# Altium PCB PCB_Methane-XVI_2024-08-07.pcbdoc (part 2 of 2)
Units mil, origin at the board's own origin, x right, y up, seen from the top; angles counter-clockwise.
Board outline 4553.3 x 5155.85 mil, 2 copper layers (Top Layer, Bottom Layer); 67 components, 58 nets, 315 pads, 114 vias.
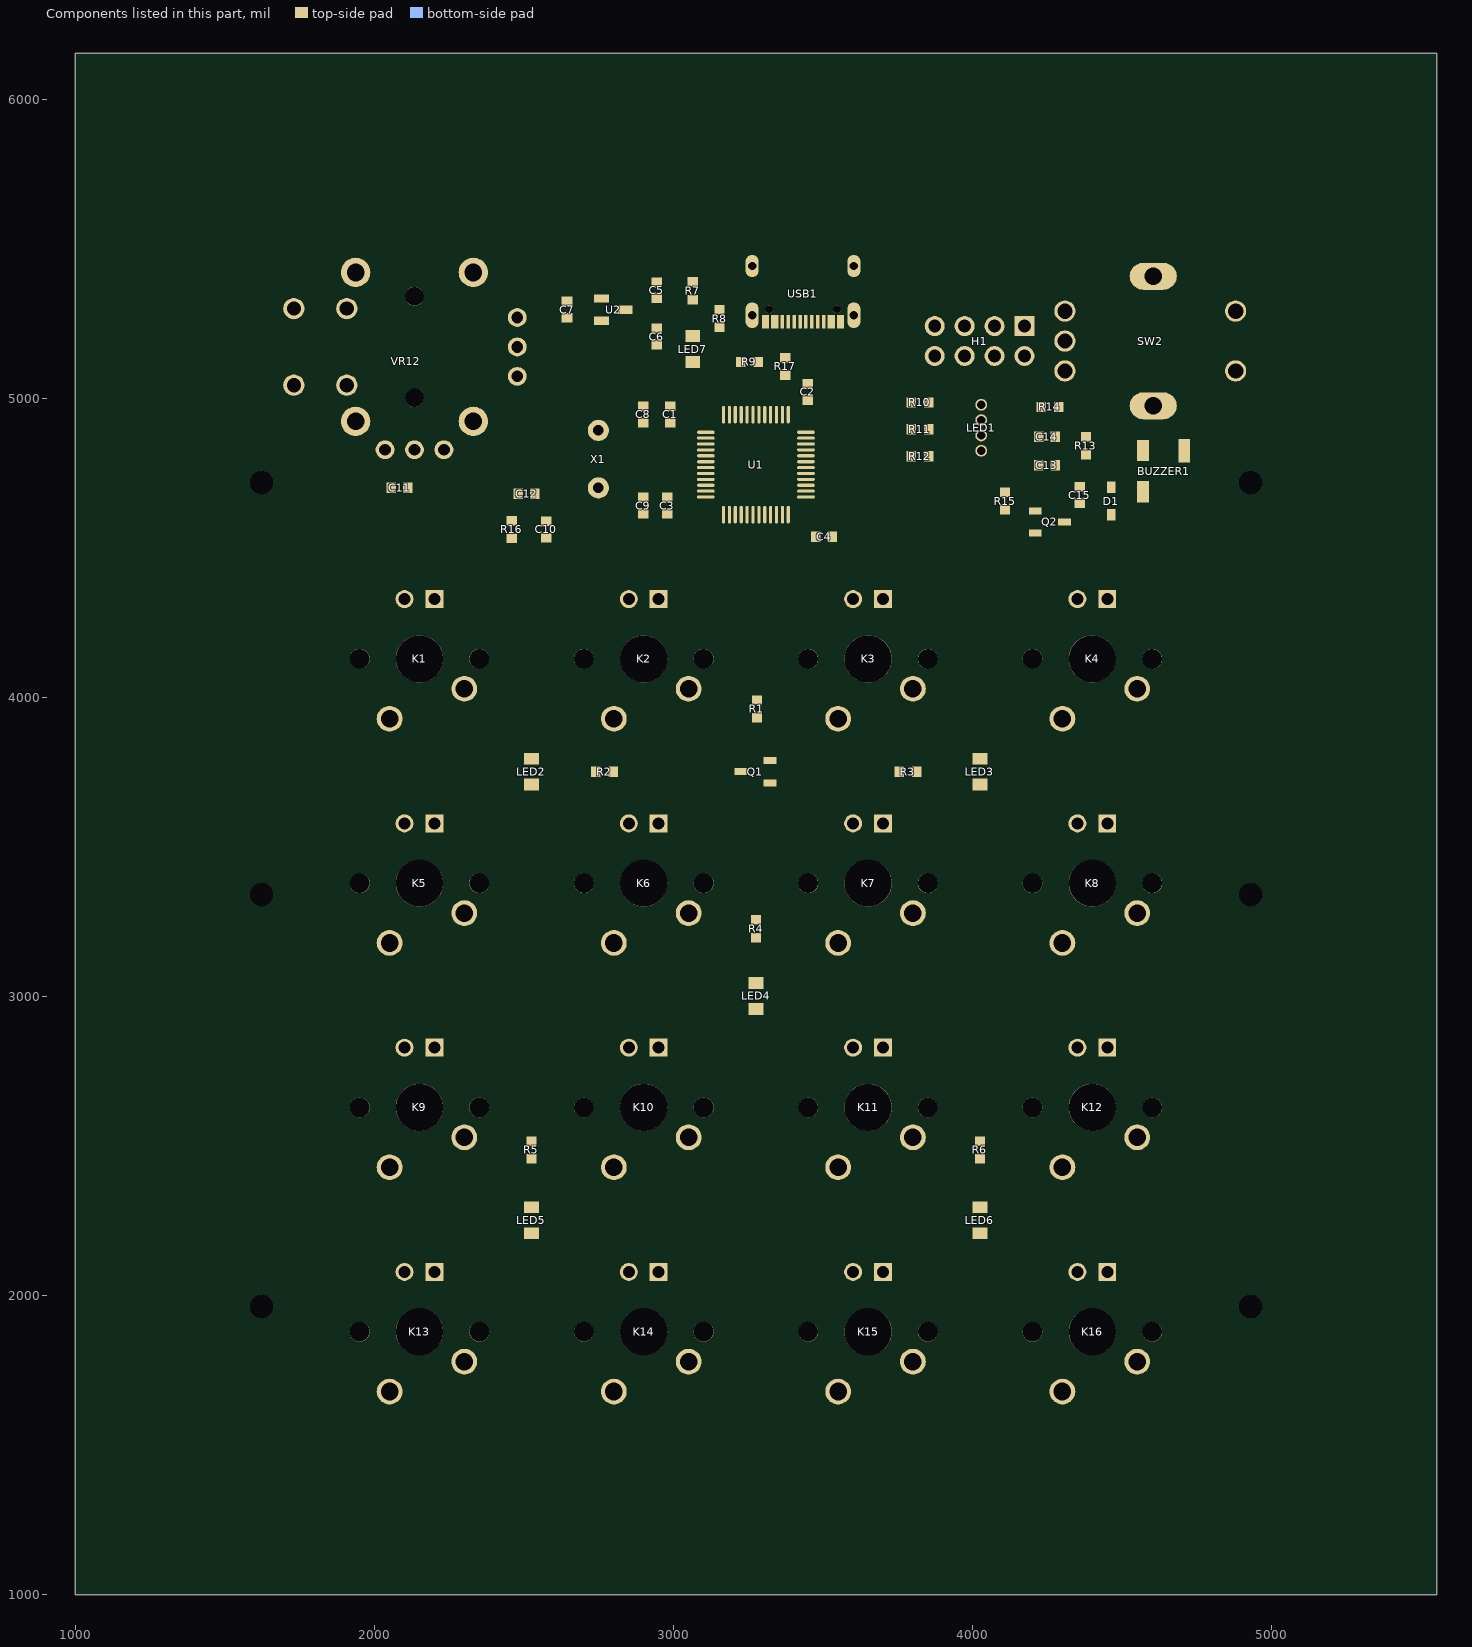
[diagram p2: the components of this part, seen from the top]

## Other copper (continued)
Bottom Layer:
  pour cut-out net S$53996: 4985,4892.94 4913.79,4821.73 4865.9,4821.73 4830,4785.83 4830,4647.94 4865,4612.94 4915,4612.94 4985,4542.94 5010,4542.94 5010,4567.94 5010,4892.94
  pour cut-out net S$53996: 4985,3514.99 4913.79,3443.78 4865.9,3443.78 4830,3407.88 4830,3269.99 4865,3234.99 4915,3234.99 4985,3164.99 5010,3164.99 5010,3189.99 5010,3514.99
  pour cut-out net S$53996: 4985,2137.04 4913.79,2065.83 4865.9,2065.83 4830,2029.93 4830,1892.04 4865,1857.04 4915,1857.04 4985,1787.04 5010,1787.04 5010,1812.04 5010,2137.04
  pour cut-out net S$53996: 1568.3,4548.14 1639.51,4619.35 1687.39,4619.35 1723.3,4655.25 1723.3,4793.14 1688.3,4828.14 1638.3,4828.14 1568.3,4898.14 1543.3,4898.14 1543.3,4873.14 1543.3,4548.14
  pour cut-out net S$53996: 1568.3,3170.19 1639.51,3241.4 1687.39,3241.4 1723.3,3277.3 1723.3,3415.19 1688.3,3450.19 1638.3,3450.19 1568.3,3520.19 1543.3,3520.19 1543.3,3495.19 1543.3,3170.19
  pour cut-out net S$53996: 1568.3,1792.24 1639.51,1863.45 1687.39,1863.45 1723.3,1899.35 1723.3,2037.24 1688.3,2072.24 1638.3,2072.24 1568.3,2142.24 1543.3,2142.24 1543.3,2117.24 1543.3,1792.24
  region net +5V: 3899.78,5120.84 3849.58,5120.84 3864.68,5097.42 3884.68,5097.42
  region net +5V: 3865.78,5175.24 3843.78,5130.12 3828.85,5152.94 3838.6,5172.94
  region net KEY1: 2330.11,3997.77 2330.07,4062.27 2360.19,4035.04 2360.2,4025.04
  region net KEY2: 3080.11,3997.77 3080.07,4062.27 3110.19,4035.04 3110.2,4025.04
  region net KEY3: 3830.11,3997.77 3830.07,4062.27 3860.19,4035.04 3860.2,4025.04
  region net KEY4: 4554.34,3987.08 4508.73,4032.69 4506.72,3992.14 4513.79,3985.07
  region net KEY5: 2330.11,3247.77 2330.07,3312.27 2360.19,3285.04 2360.2,3275.04
  region net KEY6: 3080.11,3247.77 3080.07,3312.27 3110.19,3285.04 3110.2,3275.04
  region net KEY7: 3804.34,3237.08 3758.73,3282.69 3756.72,3242.14 3763.79,3235.07
  region net KEY8: 4554.34,3237.08 4508.73,3282.69 4506.72,3242.14 4513.79,3235.07
  region net KEY9: 2330.11,2497.77 2330.07,2562.27 2360.19,2535.04 2360.2,2525.04
  region net KEY10: 3080.09,2497.75 3080.09,2562.25 3110.19,2535 3110.19,2525
  region net KEY11: 3804.34,2487.08 3758.73,2532.69 3756.72,2492.14 3763.79,2485.07
  region net KEY12: 4554.34,2487.08 4508.73,2532.69 4506.72,2492.14 4513.79,2485.07
  region net KEY13: 2330.11,1747.77 2330.07,1812.27 2360.19,1785.04 2360.2,1775.04
  region net KEY14: 3080.11,1747.77 3080.07,1812.27 3110.19,1785.04 3110.2,1775.04
  region net KEY15: 3830.11,1747.77 3830.07,1812.27 3860.19,1785.04 3860.2,1775.04
  region net KEY16: 4580.11,1747.77 4580.07,1812.27 4610.19,1785.04 4610.2,1775.04
  region net ANA1: 2132.96,4798.16 2166.35,4831.58 2168.79,4802.82 2161.72,4795.75
  region net 3V3: 2231.37,4798.16 2264.77,4831.56 2270.73,4806.34 2256.59,4792.2
  region net ANA2: 2447.18,5175.25 2480.61,5141.86 2451.85,5139.42 2444.78,5146.49
  region net 3V3: 2476.65,5106.29 2510.05,5072.89 2516.01,5098.11 2501.87,5112.25
  region net U1_7: 2971,4740 2989,4740 2985,4731.6 2975,4731.6
  region net KEY6: 3221,4400 3239,4400 3235,4391.6 3225,4391.6
  region net KEY10: 3251,4365 3269,4365 3265,4356.6 3255,4356.6
  region net KEY15: 3281,4400 3299,4400 3295,4391.6 3285,4391.6
  region net KEY11: 3311,4365 3329,4365 3325,4356.6 3315,4356.6
  region net KEY7: 3341,4400 3359,4400 3355,4391.6 3345,4391.6
  region net KEY2: 3191,4365 3209,4365 3205,4356.6 3195,4356.6
  region net KEY14: 3142.06,4413.94 3142.06,4431.94 3133.66,4427.94 3133.66,4417.94
  region net KEY13: 3110.2,4441.94 3104.69,4459.08 3097.84,4452.94 3101.05,4442.94
  region net ANA1: 3071,4615 3089,4615 3085,4606.6 3075,4606.6
  region net ANA2: 3040.75,4590.96 3028.02,4603.69 3024.91,4594.92 3031.98,4587.85
  region net SWDIO: 3474.14,4938.41 3491.12,4932.45 3490.65,4941.52 3480.18,4945.19
  region net SWCLK: 3412.94,4943.94 3412.94,4961.94 3421.34,4957.94 3421.34,4947.94
  region net SWDIO: 3562.06,4938.94 3562.06,4956.94 3553.66,4952.94 3553.66,4942.94
  region net SWCLK: 3570.75,4985.96 3558.02,4998.69 3554.91,4989.92 3561.98,4982.85
  region net EC2: 3397.94,4993.94 3397.94,5011.94 3406.34,5007.94 3406.34,4997.94
  region net EC1: 3367.94,5018.94 3367.94,5036.94 3376.34,5032.94 3376.34,5022.94
  region net EC2: 3610.75,5065.96 3598.02,5078.69 3594.91,5069.92 3601.98,5062.85
  region net EC1: 3565.75,5060.96 3553.02,5073.69 3549.91,5064.92 3556.98,5057.85
  region net KEY18: 3337.94,5043.94 3337.94,5061.94 3346.34,5057.94 3346.34,5047.94
  region net KEY18: 3560.75,5100.96 3548.02,5113.69 3544.91,5104.92 3551.98,5097.85
  region net U1_7: 2852.94,4593.94 2852.94,4611.94 2861.34,4607.94 2861.34,4597.94
  region net KEY1: 3166,4795 3184,4795 3180,4786.6 3170,4786.6
  region net KEY5: 3201,4755 3219,4755 3215,4746.6 3205,4746.6
  region net KEY9: 3236,4810 3254,4810 3250,4801.6 3240,4801.6
  region net KEY16: 3667.94,4618.94 3667.94,4636.94 3676.34,4632.94 3676.34,4622.94
  region net KEY12: 3702.94,4648.94 3702.94,4666.94 3711.34,4662.94 3711.34,4652.94
  region net KEY8: 3737.94,4678.94 3737.94,4696.94 3746.34,4692.94 3746.34,4682.94
  region net KEY4: 3772.94,4708.94 3772.94,4726.94 3781.34,4722.94 3781.34,4712.94
  region net LEDG: 3341.98,4878.69 3329.25,4865.96 3338.02,4862.85 3345.09,4869.92
  region net LEDR: 3386.98,4883.69 3374.25,4870.96 3381.46,4869.4 3388.54,4876.48
  region net 3V3: 3451.98,4918.69 3439.25,4905.96 3444.48,4899.32 3458.62,4913.46
  region net 3V3: 3432.06,4908.94 3432.06,4926.94 3423.66,4927.94 3423.66,4907.94
  region net KEY3: 3291,4735 3309,4735 3305,4726.6 3295,4726.6
  region net GATE: 3371,4365 3389,4365 3385,4356.6 3375,4356.6
  region net GATE: 3371,4095.88 3389,4095.88 3385,4104.28 3375,4104.28
  region net LEDB: 3367.94,4523.94 3367.94,4541.94 3376.34,4537.94 3376.34,4527.94
  region net LEDB: 3680.75,4770.96 3668.02,4783.69 3664.91,4774.92 3671.98,4767.85
  region net LEDR: 3630.75,4815.96 3618.02,4828.69 3614.91,4819.92 3621.98,4812.85
  region net LEDG: 3635.75,4770.96 3623.02,4783.69 3619.91,4774.92 3626.98,4767.85
  region net 3V3: 3790.75,5090.96 3778.02,5103.69 3771.38,5098.46 3785.52,5084.32
  region net 3V3: 3120.01,4955.88 3102.01,4955.87 3101.01,4964.27 3121.01,4964.28
  region net 3V3: 3551.98,4582.19 3539.25,4594.92 3544.48,4601.56 3558.62,4587.42
  region net +5V: 3530.75,5150.96 3518.02,5163.69 3511.38,5158.46 3525.52,5144.32
  region net +5V: 3537.94,5153.94 3537.94,5171.94 3546.34,5172.94 3546.34,5152.94
  region net +5V: 3936,4675.88 3954,4675.88 3955,4684.28 3935,4684.28
  region net +5V: 3145.75,5109.92 3133.02,5097.19 3126.38,5102.42 3140.52,5116.56
  region net +5V: 3152.94,5088.94 3152.94,5106.94 3161.34,5107.94 3161.34,5087.94
  region net 3V3: 2356,4660.88 2374,4660.88 2375,4669.28 2355,4669.28
  region net 3V3: 3260.75,5050.96 3248.02,5063.69 3241.38,5058.46 3255.52,5044.32
  region net 3V3: 3251,5055 3269,5055 3270,5047.94 3250,5047.94
  region net +5V: 3132.18,5123.7 3119.24,5110.76 3124.68,5104.12 3138.82,5118.26
  region net +5V: 3120.76,5135.12 3107.82,5122.18 3101.18,5127.62 3115.32,5141.76
  region net +5V: 2993.07,5278.79 2993.07,5297.09 3001.62,5297.94 3001.62,5277.94
  region net +5V: 3006.93,5278.79 3006.93,5297.09 2998.38,5297.94 2998.38,5277.94
  region net +5V: 3027.18,5288.7 3014.24,5275.76 3019.68,5269.12 3033.82,5283.26
  region net ANA2: 2441.93,4673.79 2441.93,4692.09 2433.38,4687.94 2433.38,4677.94
  region net 3V3: 2680.85,5219.87 2699.15,5219.87 2700,5211.32 2680,5211.32
  region net 3V3: 2680.85,5191.31 2699.15,5191.31 2700,5199.86 2680,5199.86
  region net 3V3: 2691.03,5171.08 2677.81,5183.74 2668.07,5181.24 2688.95,5161.24
  region net 3V3: 2702.19,5183.74 2688.97,5171.08 2691.05,5161.24 2711.93,5181.24
  region net +5V: 4016.98,4913.77 4016.98,4943.29 4003.2,4938.53 4003.2,4918.53

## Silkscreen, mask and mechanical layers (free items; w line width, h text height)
Top Overlay:
  text "DIO" at 3950,5317.94 h30
  text "CLK" at 4035,5317.94 h30
  text "3V3" at 3735,5207.94 h30
  text "GND" at 4270,5157.94 h30 r90
  text "5V" at 3745,5107.94 h30
  text "RX" at 3950,5032.94 h30
  text "TX" at 4050,5032.94 h30
  text "Methane-XVI" at 1810,4507.94 h50
Bottom Overlay:
  text "Designed by / light&electricity / V4.0" at 4745,4707.94 h50
Top Solder:
  region net GND: 2310,4607.94 2310,4567.94 2330,4587.94
  region net 3V3: 2360,4607.94 2340,4587.94 2360,4567.94
  region net +5V: 3940,4607.94 3920,4587.94 3940,4567.94
  region net GND: 3890,4607.94 3890,4567.94 3910,4587.94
